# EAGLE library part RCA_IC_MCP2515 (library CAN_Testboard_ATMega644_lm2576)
MC2515 Stand-Alone CAN Controller With SPI Interface
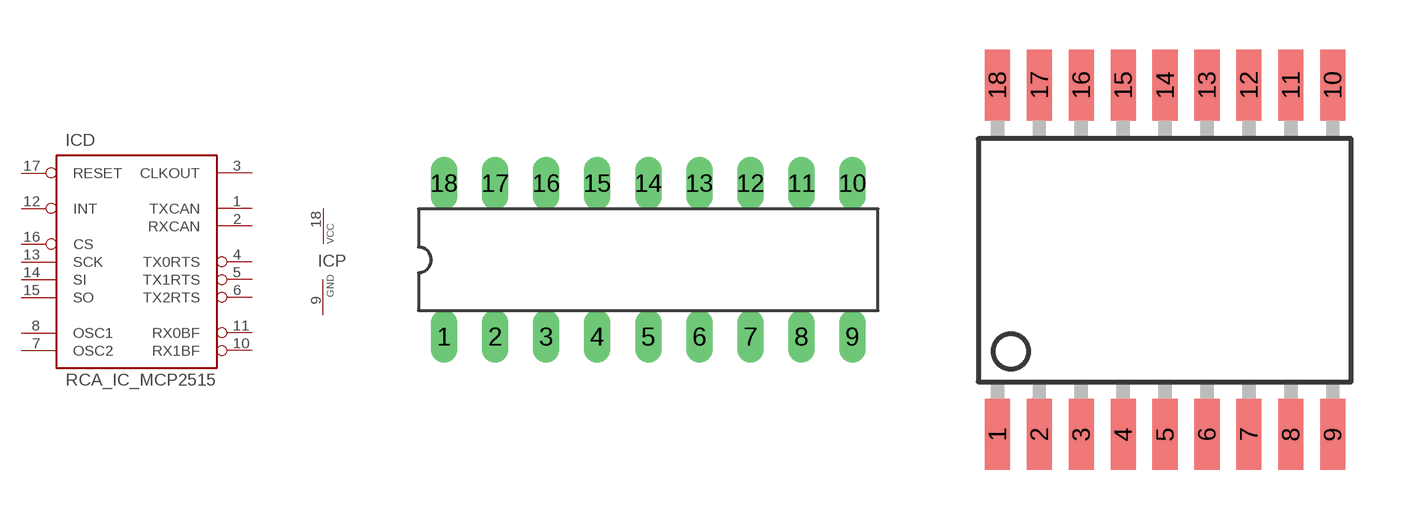
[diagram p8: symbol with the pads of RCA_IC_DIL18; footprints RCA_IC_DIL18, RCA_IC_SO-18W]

Designator prefix IC; gates D=RCA_IC_MCP2515 P=RCA_IC_VCC-GND-1

## RCA_IC_MCP2515P  [RCA_IC_DIL18]
1  D:TXCAN  out
2  D:RXCAN  in
3  D:CLKOUT  out
4  D:TX0RTS  in
5  D:TX1RTS  in
6  D:TX2RTS  in
7  D:OSC2  in
8  D:OSC1  in
9  P:GND  pwr
10  D:RX1BF  out
11  D:RX0BF  out
12  D:INT  out
13  D:SCK  in
14  D:SI  in
15  D:SO  out
16  D:CS  in
17  D:RESET  in
18  P:VCC  pwr

## RCA_IC_MCP2515SO  [RCA_IC_SO-18W]
Pads as for RCA_IC_DIL18

## RCA_IC_MCP2515ST  [RCA_IC_TSSOP20]
1  D:TXCAN  out
2  D:RXCAN  in
3  D:CLKOUT  out
4  D:TX0RTS  in
5  D:TX1RTS  in
7  D:TX2RTS  in
8  D:OSC2  in
9  D:OSC1  in
10  P:GND  pwr
11  D:RX1BF  out
12  D:RX0BF  out
13  D:INT  out
14  D:SCK  in
16  D:SI  in
17  D:SO  out
18  D:CS  in
19  D:RESET  in
20  P:VCC  pwr

## Footprint RCA_IC_DIL18 (pad centres in mm)
Dual In Line package type P
drill 0.813 long: 1 -10.16,-3.81; 2 -7.62,-3.81; 3 -5.08,-3.81; 4 -2.54,-3.81; 5 0,-3.81; 6 2.54,-3.81; 7 5.08,-3.81; 8 7.62,-3.81; 9 10.16,-3.81; 10 10.16,3.81; 11 7.62,3.81; 12 5.08,3.81; 13 2.54,3.81; 14 0,3.81; 15 -2.54,3.81; 16 -5.08,3.81; 17 -7.62,3.81; 18 -10.16,3.81

## Footprint RCA_IC_SO-18W (pad centres in mm)
Small Outline Wide Plastic Gull Wing 300-mil body, package type SO
smd 0.762 x 2.159: 1 -5.08,-5.296; 2 -3.81,-5.296; 3 -2.54,-5.296; 4 -1.27,-5.296; 5 0,-5.296; 6 1.27,-5.296; 7 2.54,-5.296; 8 3.81,-5.296; 9 5.08,-5.296; 10 5.08,5.296; 11 3.81,5.296; 12 2.54,5.296; 13 1.27,5.296; 14 0,5.296; 15 -1.27,5.296; 16 -2.54,5.296; 17 -3.81,5.296; 18 -5.08,5.296

## Footprint RCA_IC_TSSOP20 (pad centres in mm)
Thin Shrink Small Outline Plastic 20 MAX3223-MAX3243.pdf
smd 0.305 x 0.991: 1 -2.925,-2.918; 2 -2.275,-2.918; 3 -1.625,-2.918; 4 -0.975,-2.918; 5 -0.325,-2.918; 6 0.325,-2.918; 7 0.975,-2.918; 8 1.625,-2.918; 9 2.275,-2.918; 10 2.925,-2.918; 11 2.925,2.918; 12 2.275,2.918; 13 1.625,2.918; 14 0.975,2.918; 15 0.325,2.918; 16 -0.325,2.918; 17 -0.975,2.918; 18 -1.625,2.918; 19 -2.275,2.918; 20 -2.925,2.918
